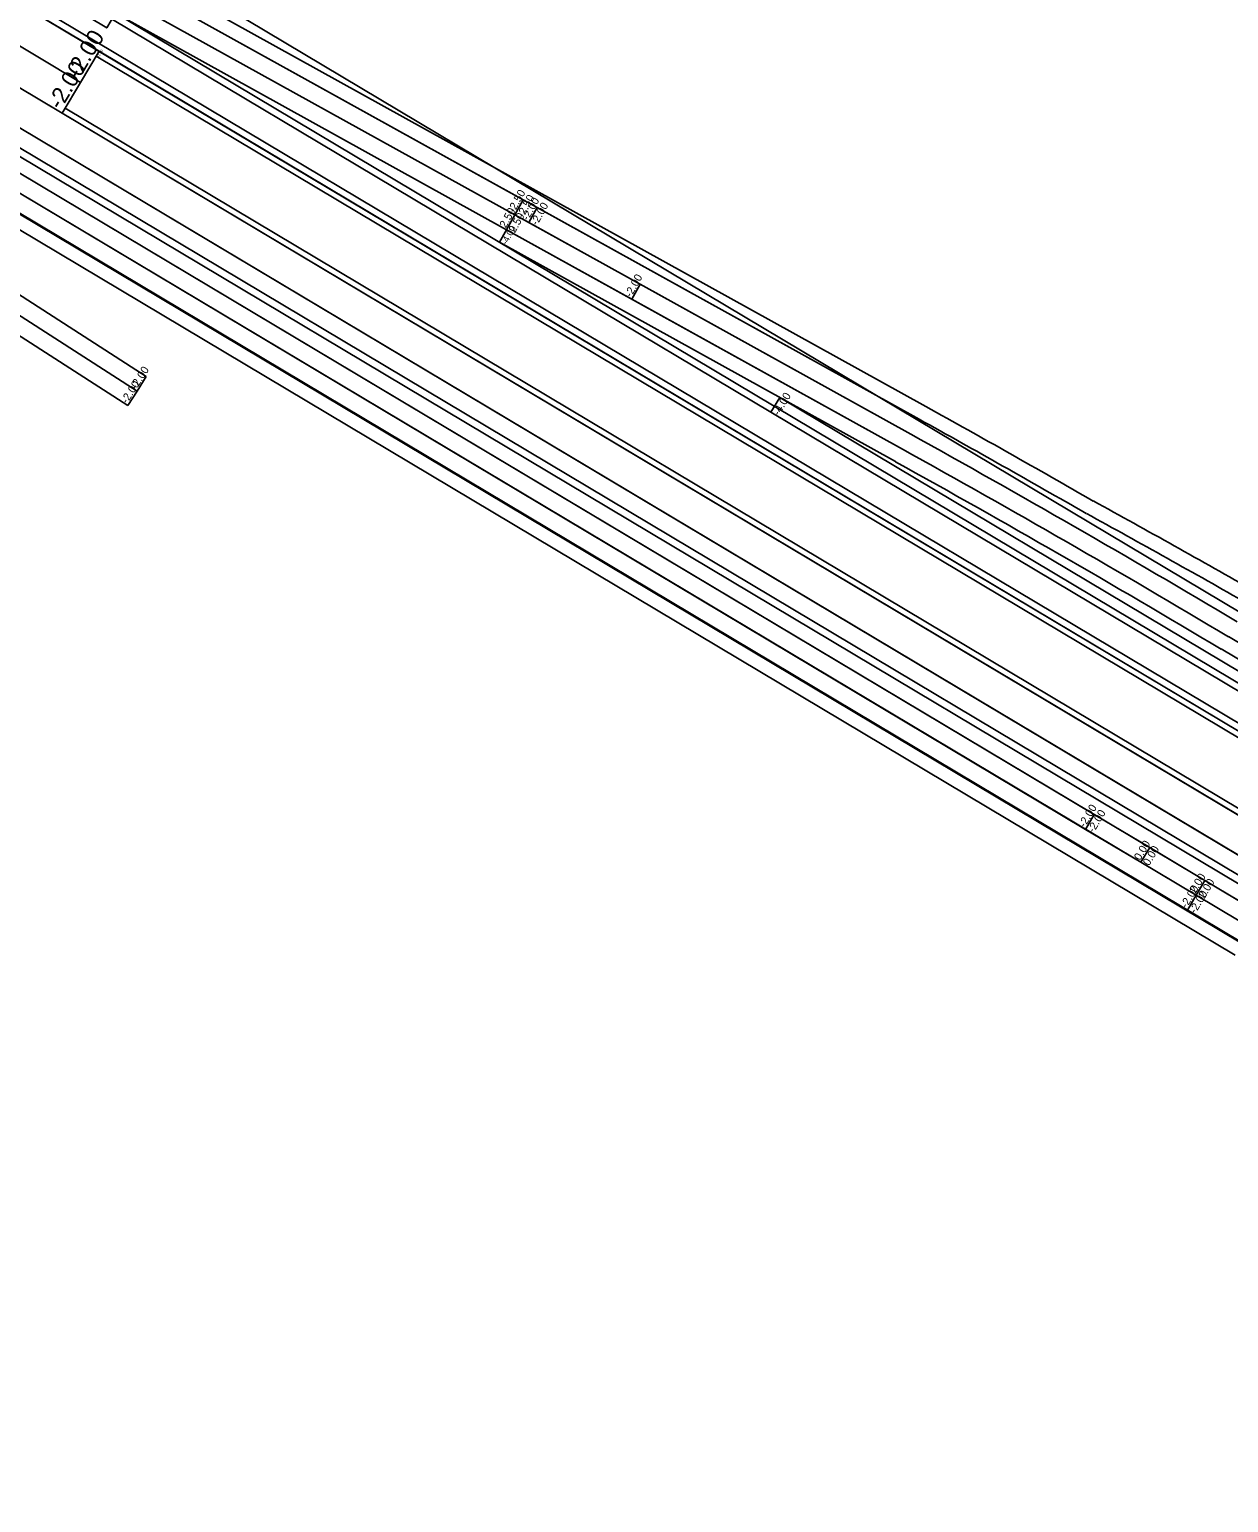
# Model space of a CAD drawing. Extents: x 2342222 to 2351711, y 366548 to 372860.
# Drawn here: x 2347057 to 2347894, y 368410 to 369439 of the extents above; entities that cross this region are included whole.
import ezdxf

# ---------------------------------------------------------------- set-up
doc = ezdxf.new("R2010")
doc.units = 0
for name, color, linetype in [('RD_HC_Cl', 7, 'Continuous'), ('RD_PD_Final_LnLine', 7, 'Continuous'), ('RD_PD_PaveShd', 7, 'Continuous'), ('RD_PD_SuperShp_BL_EB_526', 7, 'Continuous'), ('RD_PD_SuperShp_BL_WB_526', 7, 'Continuous'), ('RD_PD_SuperShp_EB_526', 7, 'Continuous'), ('RD_PD_SuperShp_REL_L-2118', 7, 'Continuous'), ('RD_PD_SuperShp_REL_LINE-3', 7, 'Continuous'), ('RD_PD_SuperShp_Rel_Line-4', 7, 'Continuous'), ('RD_PD_SuperShp_WB_526', 7, 'Continuous')]:
    doc.layers.add(name, color=color, linetype=linetype)

msp = doc.modelspace()

# ---------------------------------------------------------------- linework, layer by layer
at = {"layer": 'RD_HC_Cl'}
msp.add_line((2346606.5, 369804.5), (2348463.1, 368696.8), dxfattribs=at)
msp.add_line((2346606.5, 369804.5), (2348463.1, 368696.8), dxfattribs=at)
at = {"layer": 'RD_PD_Final_LnLine'}
msp.add_line((2346236.7, 369794.6), (2347945.2, 368775.3), dxfattribs=at)
msp.add_line((2346236.7, 369794.6), (2347945.2, 368775.3), dxfattribs=at)
at = {"layer": 'RD_PD_PaveShd'}
for p, q in [((2347103.3, 369419.8), (2348309.7, 368700)), ((2347580.8, 369181.5), (2348330, 368734.5))]:
    msp.add_line(p, q, dxfattribs=at)
at = {"layer": 'RD_PD_SuperShp_BL_EB_526'}
for p, q in [((2348273.5, 368639.7), (2346277, 369830.9)), ((2346270.8, 369820.6), (2348267.4, 368629.4)), ((2346351.1, 369814.6), (2348286, 368660.2)), ((2348273.5, 368639.7), (2346338.8, 369794)), ((2347092.4, 369401.6), (2346692.1, 369640.5)), ((2346679.2, 369618.9), (2347079.5, 369380)), ((2347079.5, 369380), (2347092.4, 369401.6)), ((2347081.6, 369383.5), (2347079.5, 369380)), ((2347079.5, 369380), (2348286, 368660.2)), ((2348288, 368663.7), (2347081.6, 369383.5))]:
    msp.add_line(p, q, dxfattribs=at)
at = {"layer": 'RD_PD_SuperShp_BL_WB_526'}
for p, q in [((2348323.9, 368724.2), (2346306.8, 369927.7)), ((2346294.5, 369907), (2348311.8, 368703.5)), ((2347105.3, 369423.3), (2346705, 369662.1)), ((2346692.1, 369640.5), (2347092.4, 369401.6)), ((2347092.4, 369401.6), (2347105.3, 369423.3)), ((2347105.3, 369423.3), (2347103.3, 369419.8)), ((2347103.3, 369419.8), (2348309.8, 368700)), ((2348311.8, 368703.5), (2347105.3, 369423.3)), ((2347574.6, 369171.2), (2347580.8, 369181.5)), ((2347580.8, 369181.5), (2347574.6, 369171.2)), ((2348330, 368734.5), (2347580.8, 369181.5)), ((2347574.6, 369171.2), (2348323.9, 368724.2))]:
    msp.add_line(p, q, dxfattribs=at)
at = {"layer": 'RD_PD_SuperShp_EB_526'}
for p, q in [((2348285.9, 368660.3), (2346335.9, 369823.7)), ((2346323.3, 369803.3), (2348273.5, 368639.7)), ((2346323.6, 369803.1), (2348273.5, 368639.7))]:
    msp.add_line(p, q, dxfattribs=at)
at = {"layer": 'RD_PD_SuperShp_REL_L-2118'}
for p, q in [((2346957.1, 369298.3), (2347131.9, 369186)), ((2347125.4, 369175.9), (2346950.6, 369288.2)), ((2347033.2, 369263.7), (2347138.3, 369196.1)), ((2347131.9, 369186), (2347026.7, 369253.6)), ((2347138.3, 369196.1), (2347131.9, 369186)), ((2347131.9, 369186), (2347125.4, 369175.9))]:
    msp.add_line(p, q, dxfattribs=at)
at = {"layer": 'RD_PD_SuperShp_REL_LINE-3'}
for p, q in [((2347921.7, 368829.6), (2346247.5, 369828.4)), ((2346242.4, 369819.8), (2347800.6, 368890.1)), ((2346242.4, 369819.8), (2347916.5, 368821)), ((2347794.5, 368879.8), (2346236.3, 369809.5)), ((2346236.3, 369809.5), (2347871.8, 368833.7)), ((2347865.6, 368823.4), (2346230.1, 369799.2)), ((2346323.7, 369743.4), (2347904.2, 368800.4)), ((2347899.1, 368791.8), (2346318.6, 369734.8)), ((2347800.6, 368890.1), (2347794.5, 368879.8)), ((2347794.5, 368879.8), (2347800.6, 368890.1)), ((2347800.6, 368890.1), (2347839.3, 368867.1)), ((2347833.1, 368856.8), (2347794.5, 368879.8)), ((2347839.3, 368867.1), (2347833.1, 368856.8)), ((2347833.1, 368856.8), (2347839.3, 368867.1)), ((2347839.3, 368867.1), (2347877.9, 368844)), ((2347871.8, 368833.7), (2347833.1, 368856.8)), ((2347877.9, 368844), (2347871.8, 368833.7)), ((2347871.8, 368833.7), (2347877.9, 368844)), ((2347877.9, 368844), (2347941.8, 368805.9)), ((2347871.8, 368833.7), (2347865.6, 368823.4)), ((2347865.6, 368823.4), (2347871.8, 368833.7)), ((2347935.6, 368795.6), (2347871.8, 368833.7)), ((2347871.8, 368833.7), (2347935.6, 368795.6)), ((2347929.5, 368785.3), (2347865.6, 368823.4))]:
    msp.add_line(p, q, dxfattribs=at)
at = {"layer": 'RD_PD_SuperShp_Rel_Line-4'}
for p, q in [((2347401.6, 369319.6), (2347128.8, 369470.8)), ((2347128.8, 369470.8), (2347678.2, 369166.4)), ((2347683, 369175.2), (2347133.6, 369479.5)), ((2347683, 369175.2), (2347133.7, 369479.5)), ((2347395.8, 369309.1), (2347123, 369460.3)), ((2347123, 369460.3), (2347395.8, 369309.1)), ((2347117.2, 369449.8), (2347390, 369298.6)), ((2347117.2, 369449.8), (2347390, 369298.6)), ((2347395.8, 369309.1), (2347401.6, 369319.6)), ((2347401.6, 369319.6), (2347395.8, 369309.1)), ((2347411.3, 369314.3), (2347401.6, 369319.6)), ((2347395.8, 369309.1), (2347390, 369298.6)), ((2347390, 369298.6), (2347395.8, 369309.1)), ((2347395.8, 369309.1), (2347390, 369298.6)), ((2347483.3, 369260.7), (2347395.8, 369309.1)), ((2347395.8, 369309.1), (2347405.5, 369303.8)), ((2347411.3, 369314.3), (2347405.5, 369303.8)), ((2347405.5, 369303.8), (2347411.3, 369314.3)), ((2347678.2, 369166.4), (2347411.3, 369314.3)), ((2347390, 369298.6), (2347385.1, 369289.9)), ((2347390, 369298.6), (2347385.1, 369289.9)), ((2347390, 369298.6), (2347477.5, 369250.2)), ((2347666.5, 369145.4), (2347390, 369298.6)), ((2347405.5, 369303.8), (2347672.4, 369155.9)), ((2347661.7, 369136.7), (2347385.1, 369289.9)), ((2347385.1, 369289.9), (2347661.7, 369136.7)), ((2347483.3, 369260.7), (2347477.5, 369250.2)), ((2347477.5, 369250.2), (2347483.3, 369260.7)), ((2347483.3, 369260.7), (2347477.5, 369250.2)), ((2347483.3, 369260.7), (2347672.4, 369155.9)), ((2347672.4, 369155.9), (2347483.3, 369260.7)), ((2347666.5, 369145.4), (2347477.5, 369250.2)), ((2347477.5, 369250.2), (2347666.5, 369145.4)), ((2347894.4, 369014.4), (2348368.9, 368731.3)), ((2348368.9, 368731.3), (2347894.4, 369014.4)), ((2347894.4, 369014.4), (2348368.9, 368731.3)), ((2347889.2, 369005.8), (2348363.8, 368722.7)), ((2347889.2, 369005.8), (2348363.8, 368722.7))]:
    msp.add_line(p, q, dxfattribs=at)
for centre, radius, start, end in [((2343690.2, 361967.9), 8239.3, 60.0802, 61.01367), ((2343690.2, 361967.9), 8239.3, 60.0802, 61.01367), ((2343690.2, 361967.9), 8229.3, 60.07911, 61.01367), ((2343690.2, 361967.9), 8229.3, 60.07911, 61.01367), ((2343690.2, 361967.9), 8217.3, 59.17851, 61.01367), ((2343690.2, 361967.9), 8217.3, 59.17851, 61.01367), ((2343690.2, 361967.9), 8217.3, 59.17851, 61.01367), ((2343690.2, 361967.9), 8205.3, 59.17851, 61.01367), ((2343690.2, 361967.9), 8205.3, 59.17851, 61.01367), ((2343690.2, 361967.9), 8205.3, 59.17851, 61.01367), ((2343690.2, 361967.9), 8195.3, 59.17851, 61.01367), ((2343690.2, 361967.9), 8195.3, 59.17851, 61.01367), ((2343906.6, 362012.6), 8084.4, 60.3362, 61.25045), ((2343906.6, 362012.6), 8084.4, 60.3362, 61.25045), ((2343906.6, 362012.6), 8094.4, 60.3362, 61.25011), ((2343906.6, 362012.6), 8094.4, 60.3362, 61.25011)]:
    msp.add_arc(centre, radius, start, end, dxfattribs=at)
at = {"layer": 'RD_PD_SuperShp_WB_526'}
msp.add_line((2346189.9, 369975), (2349293.2, 368123.5), dxfattribs=at)
msp.add_lwpolyline([(2349305.5, 368144.1), (2347116.8, 369450), (2347110.7, 369439.7), (2346196.1, 369985.3)], dxfattribs=at)

# ---------------------------------------------------------------- texts
at = {"layer": 'RD_PD_SuperShp_BL_EB_526'}
msp.add_text('-2.00', height=11.58, rotation=59.1729, dxfattribs=at).set_placement((2347078.5, 369381.8))
at = {"layer": 'RD_PD_SuperShp_BL_WB_526'}
for s, height, rotation, p in [('-2.00', 11.58, 59.1691, (2347091.4, 369403.4)), ('-2.00', 1.84, 59.1191, (2347105.2, 369418.9)), ('-4.00', 5.52, 59.2014, (2347580.3, 369168.4))]:
    msp.add_text(s, height=height, rotation=rotation, dxfattribs=at).set_placement(p)
at = {"layer": 'RD_PD_SuperShp_REL_L-2118'}
for p in [(2347131.4, 369186.8), (2347124.9, 369176.8)]:
    msp.add_text('-2.00', height=5.52, rotation=57.2694, dxfattribs=at).set_placement(p)
at = {"layer": 'RD_PD_SuperShp_REL_LINE-3'}
for s, p in [('-2.00', (2347794, 368880.7)), ('-2.00', (2347800.2, 368877)), ('0.00', (2347832.6, 368857.6)), ('0.00', (2347838.8, 368853.9)), ('2.00', (2347871.3, 368834.6)), ('2.00', (2347877.5, 368830.9)), ('-2.00', (2347865.1, 368824.3)), ('-2.00', (2347871.3, 368820.6))]:
    msp.add_text(s, height=5.52, rotation=59.1785, dxfattribs=at).set_placement(p)
at = {"layer": 'RD_PD_SuperShp_Rel_Line-4'}
for s, height, rotation, p in [('-2.50', 5.52, 61.0137, (2347395.3, 369310)), ('-2.50', 5.52, 61.0137, (2347401.6, 369306.5)), ('-2.00', 5.52, 61.0137, (2347405, 369304.6)), ('-2.00', 5.52, 61.0137, (2347411.3, 369301.1)), ('2.50', 5.52, 61.026, (2347389.5, 369299.5)), ('2.50', 5.52, 61.026, (2347395.8, 369296)), ('-4.00', 4.6, 61.0137, (2347390, 369287.7)), ('-2.00', 5.52, 61.0137, (2347477, 369251))]:
    msp.add_text(s, height=height, rotation=rotation, dxfattribs=at).set_placement(p)

doc.saveas('drawing.dxf')
